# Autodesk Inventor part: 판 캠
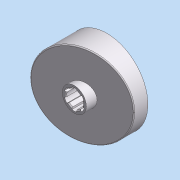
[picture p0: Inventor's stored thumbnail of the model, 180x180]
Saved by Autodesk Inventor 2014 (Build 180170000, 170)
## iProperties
Company: 한국ATC센터
Created: 2012-05
Part Number: 판 캠
Document SubType Name: 모델링
Designer: KYOUNG IL JANG
Mass: 681.586 g
Surface Area: 331.303 cm^2
Volume: 86.8262 cm^3
Density: 7.85 g/cm^3
Material: 강
Appearance: 알루미늄 - 평지
변환 표준: STEP AP214IS
파일 이름: C:\Users\SeoGD\Desktop\?쒗뿕\??stp
전처리기: Build: 253, Release: 2010 SP1 - Date: Wed 07/29/2009
전송 단위: 밀리미터
불확실성: 0.01
Author: KYOUNG IL JANG
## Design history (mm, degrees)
node "작업 평면4"
sketch "스케치1"
  geometry: C1 r 44.5 at (0, 0); 1 further point
  constraints: 1 centre point, 1 coincident
  dimensions: "d25" = 89 diameter of C1
extrude "돌출1" new body sketch "스케치1" distance "d1" = 40; taper "d2" = 0 deg
sketch "스케치2"
  geometry: L1 (-44.5, 15)-(44.5, 38.847); L2 (-44.5, 0)-(-44.5, 40) reference; L3 (-44.5, 40)-(44.5, 40) reference; L4 (44.5, 0)-(44.5, 40) reference; 1 further point
  constraints: 2 end point, 2 point on line
  dimensions: "d26" = 15 distance of L2.start L1.start; "d27" = 75 deg angle of L1 L2
extrude "돌출2" cut sketch "스케치2" stored distance "d5" = 40; taper "d6" = 0 deg
node "작업 평면1"
sketch "스케치3"
  geometry: C1 r 13 at (0, 0); 1 further point
  constraints: 1 centre point, 1 coincident
  dimensions: "d9" = 26 diameter of C1
extrude "돌출3" join sketch "스케치3" distance "d10" = 38; taper "d11" = 0 deg
hole "구멍1" diameter "d14" = 18; stored, may be unused: countersink angle "d18" = 90 deg, drill point angle "d20" = 118 deg; dims "d12" = 10, "d13" = 10, "d15" = 6, "d16" = 4, "d17" = 2, "d19" = 8
feature "쉘2" dims "d29" = 5
sketch "스케치6"
  geometry: C1 r 17.5 at (0, 0); C2 r 14 at (0, 0) reference; 1 further point
  constraints: 1 centre point, 1 coincident
  dimensions: "d28" = 35 diameter of C1
extrude "돌출4" join sketch "스케치6" stored distance "d30" = 38; taper "d31" = 0 deg
fillet "모깎기1" dims "d32" = 3
chamfer "모따기1" distance "d21" = 1; stored, may be unused: second distance "d22" = 2, angle "d23" = 45 deg
sketch "스케치7"
  geometry: L1 (-12.374, 12.374)-(-27.931, 27.931); A1 r 39.5 centre (0, 0) between (-27.931, 27.931) and (0, 39.5) reference; 2 further points
  constraints: 2 end point, 2 point on circle, 1 point on line, 1 vertical alignment, 2 other
  dimensions: "d33" = 45 deg dimension on point (0, 0) L1.start A1.end
feature "리브1" sketch "스케치7" dims "d34" = 5, "d35" = 1, "d36" = 0
fillet "모깎기2" dims "d37" = 3
sketch "스케치8"
  geometry: L1 (2.5, 10.712)-(2.5, 8.646); L2 (-2.5, 10.712)-(-2.5, 8.646); A1 r 11 centre (0, 0) between (2.5, 10.712) and (-2.5, 10.712); A2 r 9 centre (0, 0) between (2.5, 8.646) and (-2.5, 8.646) reference; 1 further point
  constraints: 4 end point, 4 point on circle, 2 parallel, 1 centre point, 1 coincident, 1 vertical
  dimensions: "d41" = 22 diameter of A1; "d42" = 5 distance between parallel lines of L1 L2
extrude "돌출5" cut sketch "스케치8" stored distance "d43" = 38; taper "d44" = 0 deg
fillet "모깎기3" dims "d48" = 1
node "솔리드1"
node "솔리드 본체"
node "곡면 본체"
pattern_circular "원형 패턴1" dims angle "d39" = 360 deg
pattern_circular "원형 패턴2" dims angle "d46" = 360 deg
node "솔리드2"
